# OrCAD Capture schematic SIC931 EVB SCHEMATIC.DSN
size C
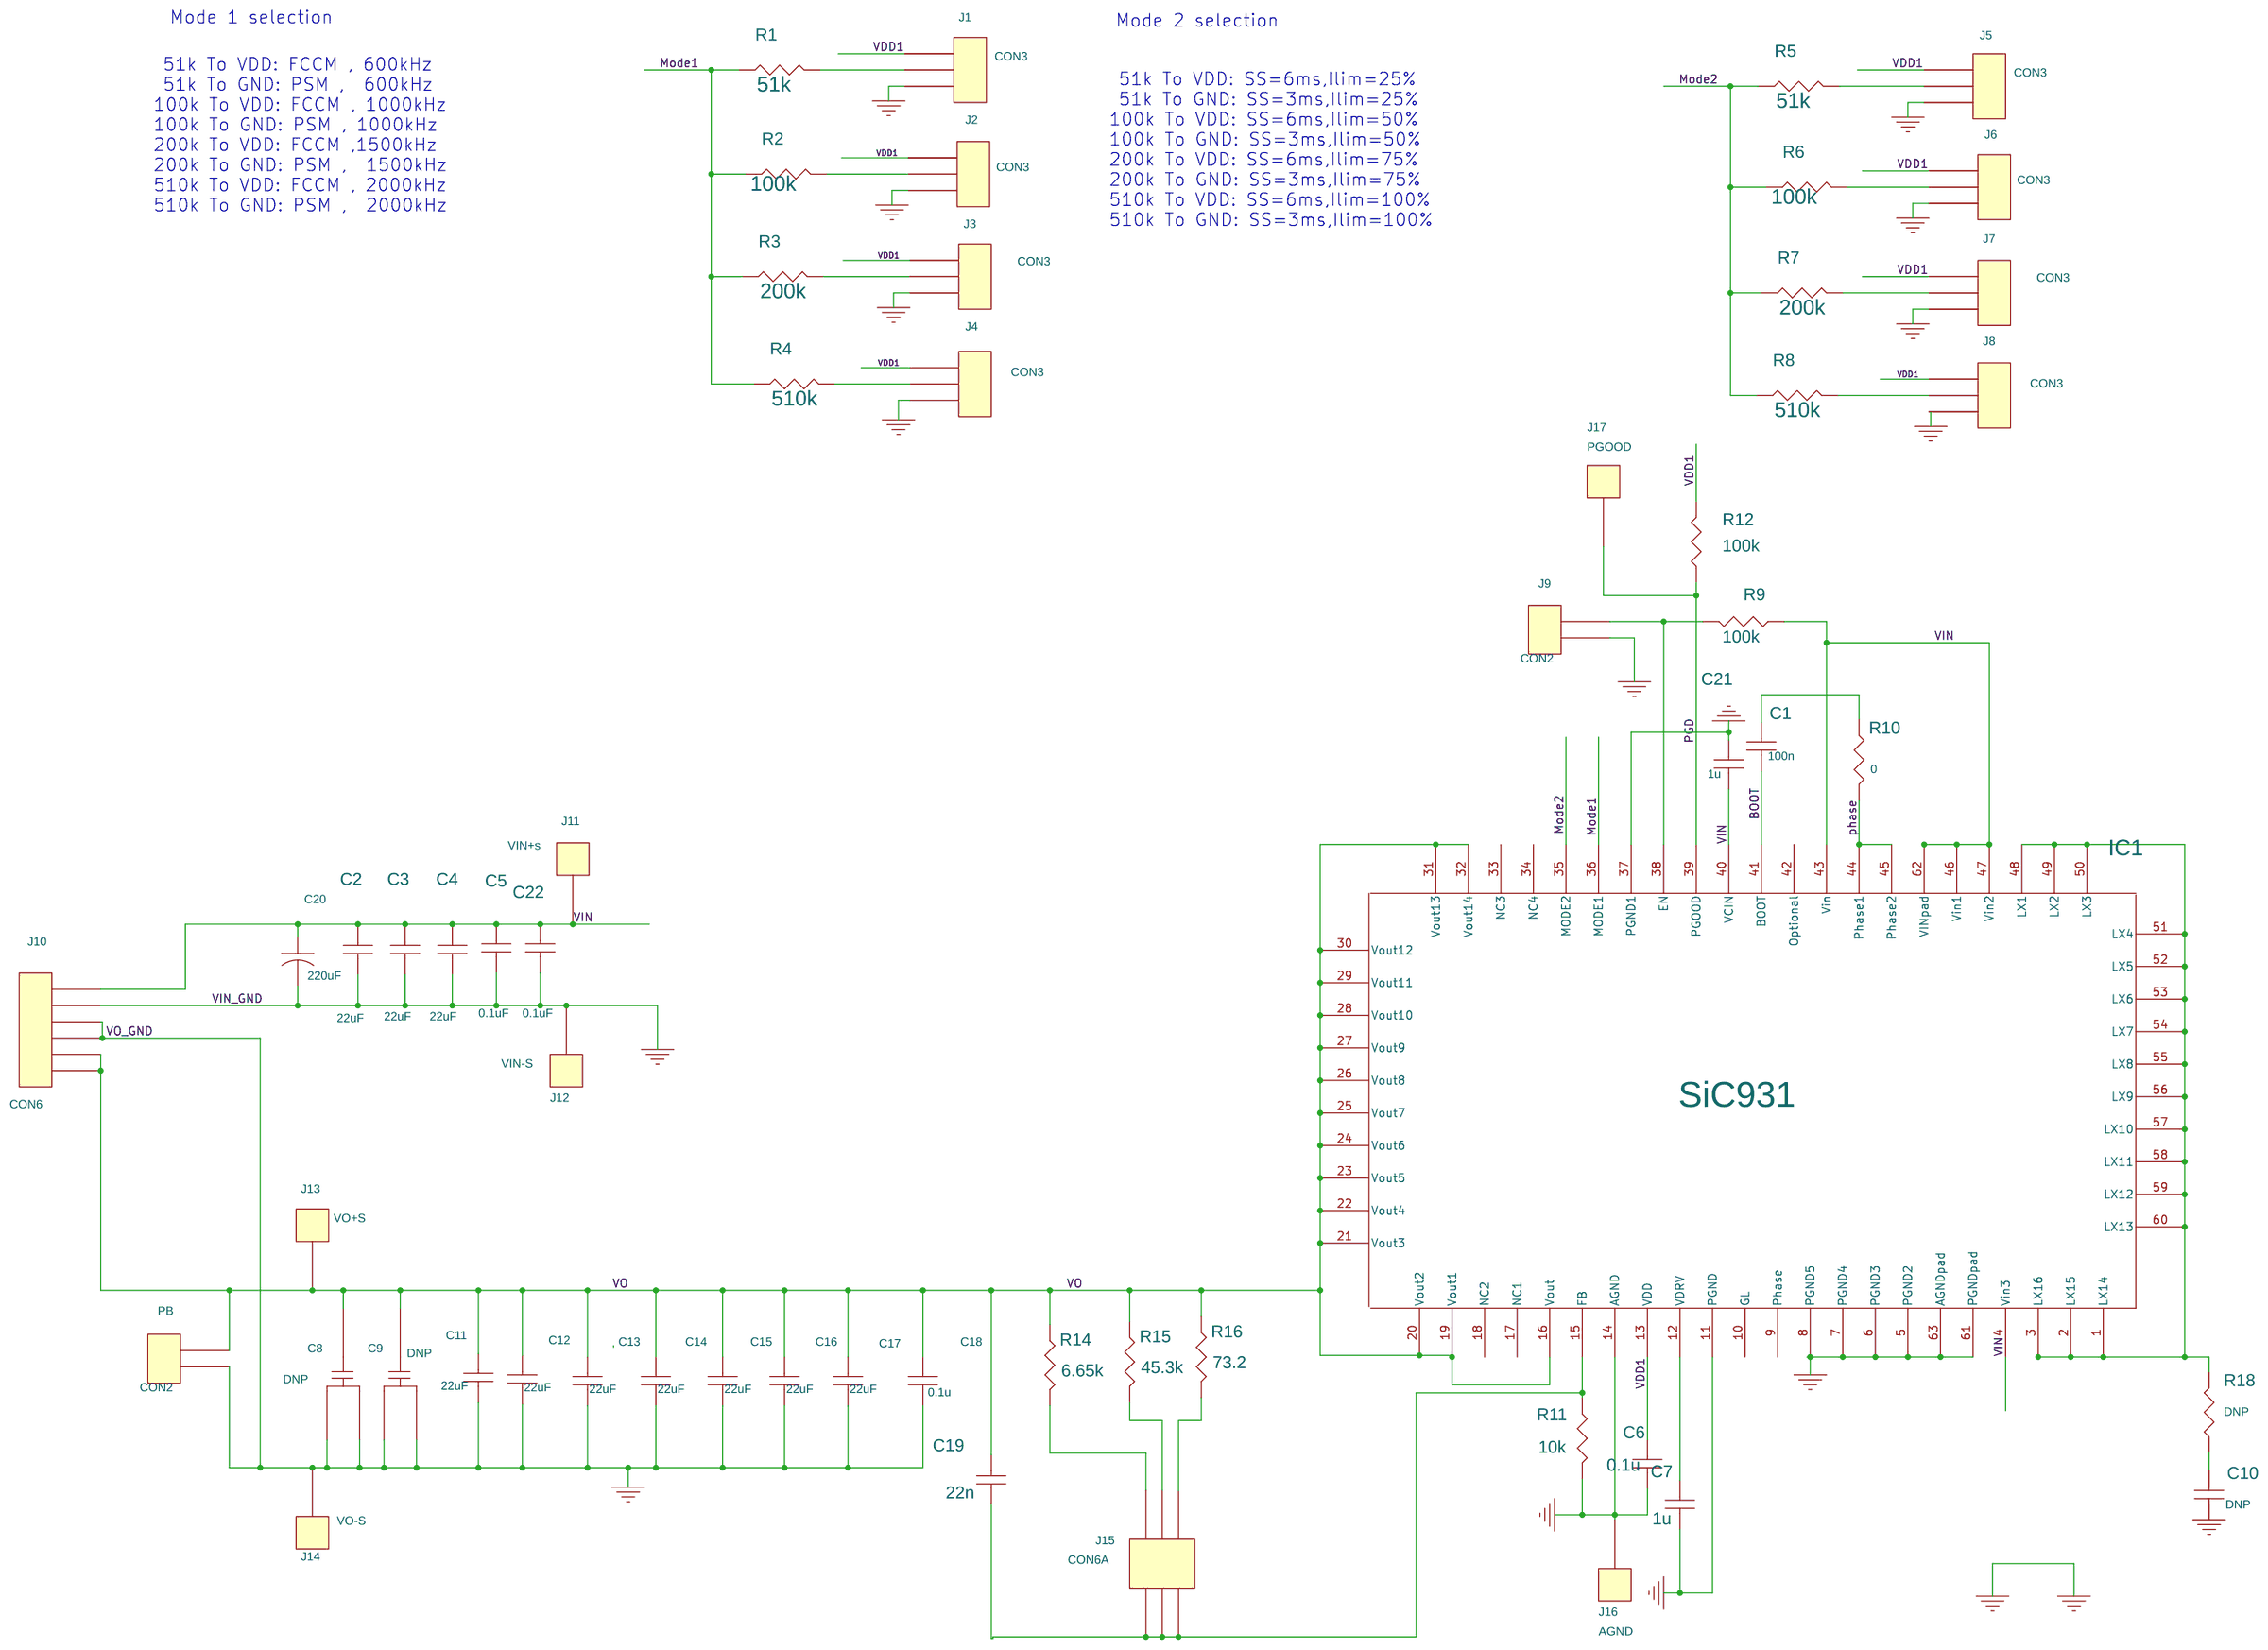
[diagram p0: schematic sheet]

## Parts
C1  100n  [C0402-TDK1]
C2  22uF  [C1210-TDK]
C3  22uF  [C1210-TDK]
C4  22uF  [C1210-TDK]
C5  0.1uF  [C0402-TDK]
C6  0.1u  [C0402-TDK1]
C7  1u  [C0603-TDK1]
C8  DNP  [poscap]
C9  DNP  [poscap]
C10  DNP  [C0603-TDK1]
C11  22uF  [C1210-TDK]
C12  22uF  [C1210-TDK]
C13  22uF  [C1210-TDK]
C14  22uF  [C1210-TDK]
C15  22uF  [C1210-TDK]
C16  22uF  [C1210-TDK]
C17  22uF  [C1210-TDK]
C18  0.1u  [C0603-TDK1]
C19  22n  [C0603-TDK1]
C20  220uF  [CAP10p2x5]
C21  1u  [C0603-TDK1]
C22  0.1uF  [C0402-TDK]
IC1  SiC931  [sic931a]
J1  CON3  [minijumper3]
J2  CON3  [minijumper3]
J3  CON3  [minijumper3]
J4  CON3  [minijumper3]
J5  CON3  [minijumper3]
J6  CON3  [minijumper3]
J7  CON3  [minijumper3]
J8  CON3  [minijumper3]
J9  CON2  [minijumper2]
J10  CON6  [con6]
J11  VIN+s  [TP30]
J12  VIN-S  [TP30]
J13  VO+S  [TP30]
J14  VO-S  [TP30]
J15  CON6A  [MINIJUMPER2X3]
J16  AGND  [TP30]
J17  PGOOD  [TP30]
PB  CON2  [2probe]
R1  51k  [R0402-vishay1]
R2  100k  [R0402-vishay1]
R3  200k  [R0402-vishay1]
R4  510k  [R0402-vishay1]
R5  51k  [R0402-vishay1]
R6  100k  [R0402-vishay1]
R7  200k  [R0402-vishay1]
R8  510k  [R0402-vishay1]
R9  100k  [R0402-vishay1]
R10  0  [R0402-vishay1]
R11  10k  [R0603-vishay]
R12  100k  [R0402-vishay1]
R14  6.65k  [R0603-vishay]
R15  45.3k  [R0603-vishay]
R16  73.2  [R0603-vishay]
R18  DNP  [R1206-vishay]

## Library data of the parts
C1 C6 C11-C19 C21 = CAPACITOR_NON-POL
C2-C4 = CAPACITOR_NON-POL: Part number: HMK325B7225KN-T
C5 C22 = CAPACITOR_NON-POL: Part number: GCM188R72A103KA37D
C7 C10 = CAP_NP: Voltage: 50V
C8 C9 = POSCAP
C20 = CAP
IC1 = SiC931
J1-J8 = CON3: Part number: S9014E-03-ND
J9 PB = CON2
J10 = CON6: PN: 277-1581-ND
J11-J14 J16 J17 = CON1: MANUFACTURER: Keystone; Part Number: 1573-3
J15 = CON6A
R1-R8 R10 R12 R14-R16 = R
R9 R11 R18 = RESISTOR

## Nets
GND_POWER: C2.2 C3.2 C4.2 C5.2 C6.2 C7.2 C8.2(N1) C8.3(N2) C9.2(N1) C9.3(N2) C10.2 C11.2 C12.2 C13.2 C14.2 C15.2 C16.2 C17.2 C18.2 C20.2 C21.1 C22.2 IC1.5(PGND2) IC1.6(PGND3) IC1.7(PGND4) IC1.8(PGND5) IC1.11(PGND) IC1.14(AGND) IC1.37(PGND1) IC1.61(PGNDpad) IC1.63(AGNDpad) J1.3 J2.3 J3.3 J4.3 J5.3 J6.3 J7.3 J8.3 J9.2 J10.2 J10.3 J10.4 J12.1 J14.1 J16.1 PB.2 R11.2
VDD1: C6.1 IC1.13(VDD) J1.1 J2.1 J3.1 J4.1 J5.1 J6.1 J7.1 J8.1 R12.2
VIN: C2.1 C3.1 C4.1 C5.1 C20.1 C21.2 C22.1 IC1.4(Vin3) IC1.40(VCIN) IC1.43(Vin) IC1.46(Vin1) IC1.47(Vin2) IC1.62(VINpad) J10.1 J11.1 R9.2
BOOT: C1.2 IC1.41(BOOT)
Mode1: IC1.36(MODE1) R1.1 R2.1 R3.1 R4.1
Mode2: IC1.35(MODE2) R5.1 R6.1 R7.1 R8.1
PGD: IC1.39(PGOOD) J17.1 R12.1
phase: IC1.44(Phase1) IC1.45(Phase2) R10.2
VO: C8.1(P) C9.1(P) C11.1 C12.1 C13.1 C14.1 C15.1 C16.1 C17.1 C18.1 C19.2 IC1.16(Vout) IC1.19(Vout1) IC1.20(Vout2) IC1.21(Vout3) IC1.22(Vout4) IC1.23(Vout5) IC1.24(Vout6) IC1.25(Vout7) IC1.26(Vout8) IC1.27(Vout9) IC1.28(Vout10) IC1.29(Vout11) IC1.30(Vout12) IC1.31(Vout13) IC1.32(Vout14) J10.5 J10.6 J13.1 PB.1 R14.1 R15.1 R16.1
N10592056: J1.2 R1.2
N10592279: J2.2 R2.2
N10592308: J3.2 R3.2
N10592330: J4.2 R4.2
N10602058: J5.2 R5.2
N10602062: J6.2 R6.2
N10602066: J7.2 R7.2
N10602070: J8.2 R8.2
N10738499: C7.1 IC1.12(VDRV)
N10742884: J15.3 R15.2
N10742888: J15.5 R16.2
N10742896: J15.1 R14.2
N10742948: C19.1 IC1.15(FB) J15.2 J15.4 J15.6 R11.1
N10743645: C1.1 R10.1
N10744089: IC1.1(LX14) IC1.2(LX15) IC1.3(LX16) IC1.48(LX1) IC1.49(LX2) IC1.50(LX3) IC1.51(LX4) IC1.52(LX5) IC1.53(LX6) IC1.54(LX7) IC1.55(LX8) IC1.56(LX9) IC1.57(LX10) IC1.58(LX11) IC1.59(LX12) IC1.60(LX13) R18.2
N10747860: IC1.38(EN) J9.1 R9.1
N10760962: C10.1 R18.1

Not connected (* = marked no-connect by the designer): IC1 9(Phase) 10(GL) 17(NC1) 18(NC2) 33(NC3) 34(NC4) 42(Optional)

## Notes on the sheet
- Mode 1 selection
- Mode 2 selection
- 51k To VDD: FCCM , 600kHz
   51k To GND: PSM ,  600kHz
  100k To VDD: FCCM , 1000kHz
  100k To GND: PSM , 1000kHz
  200k To VDD: FCCM ,1500kHz
  200k To GND: PSM ,  1500kHz
  510k To VDD: FCCM , 2000kHz
  510k To GND: PSM ,  2000kHz
- 51k To VDD: SS=6ms,Ilim=25%
   51k To GND: SS=3ms,Ilim=25%
  100k To VDD: SS=6ms,Ilim=50%
  100k To GND: SS=3ms,Ilim=50%
  200k To VDD: SS=6ms,Ilim=75%
  200k To GND: SS=3ms,Ilim=75%
  510k To VDD: SS=6ms,Ilim=100%
  510k To GND: SS=3ms,Ilim=100%
